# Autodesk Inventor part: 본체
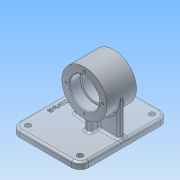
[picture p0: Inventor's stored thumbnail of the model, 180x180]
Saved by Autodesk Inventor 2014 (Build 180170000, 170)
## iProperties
Created: 2019-09
Part Number: 본체
Material: 알루미늄 6061
Document SubType Name: Modeling
Designer: net
Density: 2.71 g/cm^3
Appearance: 알루미늄 - 평지
Mass: 556.75 g
Surface Area: 497.149 cm^2
Volume: 205.443 cm^3
Author: net
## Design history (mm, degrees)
sketch "스케치1"
  geometry: L1 (-21, 0)-(21, 0); L2 (-21, 21)-(-6.3, 21); L3 (-6, 20.7)-(-6, 18); L4 (-6, 18)-(6, 18); L5 (6, 18)-(6, 20.7); L6 (6.3, 21)-(21, 21); L7 (21, 21)-(21, 32); L8 (21, 32)-(-21, 32); L9 (-21, 32)-(-21, 21); A1 r 0.3 centre (-6.3, 20.7) between (-6, 20.7) and (-6.3, 21); A2 r 0.3 centre (6.3, 20.7) between (6.3, 21) and (6, 20.7); 5 further points
  constraints: 18 end point, 6 parallel, 4 point on circle, 4 tangent, 3 collinear, 3 midpoint, 2 centre point, 2 point on line, 2 vertical alignment, 1 coincident, 1 equal radius, 1 horizontal, 1 perpendicular
  dimensions: "d0" = 42 distance of L1.start L1.end; "d1" = 15 distance of L2.start point (-6, 21); "d2" = 42 diameter of L2 L1; "d3" = 64 diameter of L8 L1; "d4" = 36 diameter of L4 L1; "d5" = 0.3 radius of A1
revolve "회전1" sketch "스케치1" stored, may be unused: angle "d6" = 90 deg
node "작업 평면1"
sketch "스케치2"
  geometry: L1 (21, 32)-(21, -32) reference; L2 (-21, 32)-(-21, -32) reference; L3 (51, -62)-(-51, -62); L4 (-63, -50)-(-63, 24); L5 (-51, 36)-(51, 36); L6 (63, 24)-(63, -50); L7 (21, -32)-(-21, -32) reference; L8 (21, 32)-(-21, 32) reference; A1 r 12 centre (51, 24) between (63, 24) and (51, 36); A2 r 12 centre (-51, 24) between (-51, 36) and (-63, 24); A3 r 12 centre (-51, -50) between (-63, -50) and (-51, -62); A4 r 12 centre (51, -50) between (51, -62) and (63, -50); 4 further points
  constraints: 8 end point, 8 point on circle, 8 tangent, 6 point on line, 4 centre point, 3 equal radius, 2 parallel, 1 horizontal, 1 perpendicular
  dimensions: "d8" = 98 distance of point (-63, -62) point (-63, 36); "d9" = 126 distance of point (63, -62) point (-63, -62); "d10" = 63 distance from line of L4 point (0, 0); "d11" = 62 distance from line of L3 point (0, 0); "d12" = 12 radius of A1
extrude "돌출1" join sketch "스케치2" distance "d13" = 9; taper "d14" = 0 deg
sketch "스케치3"
  geometry: L1 (4, -32)-(-4, -32); L2 (-4, -32)-(-4, 32); L3 (-4, 32)-(4, 32); L4 (4, 32)-(4, -32); L5 (4, -32)-(-4, 32); L6 (-4, -32)-(4, 32); L7 (-17, 4)-(17, 4); L8 (17, 4)-(17, -4); L9 (17, -4)-(-17, -4); L10 (-17, -4)-(-17, 4); L11 (-17, 4)-(17, -4); L12 (17, 4)-(-17, -4); L13 (-21, 32)-(21, 32) reference; L14 (-21, -32)-(21, -32) reference; 4 further points
  constraints: 24 end point, 6 midpoint, 4 parallel, 2 collinear, 2 horizontal, 2 perpendicular, 1 coincident
  dimensions: "d15" = 8 distance of L2.end L3.end; "d16" = 8 distance of L7.end L8.end (= d15); "d17" = 34 distance of L7.start L7.end
extrude "돌출2" join sketch "스케치3" stored distance "d18" = 9; taper "d19" = 0 deg
chamfer "모따기1" distance "d20" = 1; stored, may be unused: second distance "d21" = 2, angle "d22" = 45 deg
fillet "모깎기1" dims "d23" = 3
sketch "스케치4"
  geometry: A1 r 9 centre (51, -24) between (51, -33) and (60, -24) reference; A2 r 9 centre (51, 50) between (60, 50) and (51, 59) reference; A3 r 9 centre (-51, 50) between (-51, 59) and (-60, 50) reference; A4 r 9 centre (-51, -24) between (-60, -24) and (-51, -33) reference; 5 further points
  constraints: 4 coincident
hole "구멍1" sketch "스케치4" at (-51, 50), (51, 50), (51, -24), (-51, -24) diameter "d24" = 4.5; stored, may be unused: countersink angle "d28" = 90 deg, drill point angle "d30" = 118 deg; dims "d25" = 6, "d26" = 8, "d27" = 4.4, "d29" = 8
sketch "스케치5"
  geometry: C1 r 32 at (0, 0) reference; 1 further point
  constraints: 1 vertical alignment
  dimensions: "d31" = 26 distance of C1.centre point (0, 26)
hole "구멍2" sketch "스케치5" at (0, 26) diameter "d32" = 3.242; stored, may be unused: countersink angle "d36" = 90 deg, drill point angle "d38" = 118 deg; dims "d33" = 8, "d34" = 8, "d35" = 4.4, "d37" = 10
sketch "스케치6"
  geometry: L1 (51, 62)-(-51, 62) reference; L2 (63, -24)-(63, 50) reference; 2 further points
  constraints: 1 other
  dimensions: "d42" = 10 distance from line of L1 point (0, 52); "d43" = 63 distance from line of L2 point (0, 52)
feature "엠보싱1" sketch "스케치6" dims "d0" = 42, "d1" = 15, "d2" = 42, "d3" = 64, "d4" = 36, "d5" = 0.3, "d8" = 98, "d9" = 126, "d10" = 63, "d11" = 62, "d12" = 12, "d44" = 1, "d45" = 0
node "솔리드1"
pattern_circular "원형 패턴1" dims angle "d40" = 360 deg
mirror "대칭1"
node "투영된 루프1"
other parameters: "d7" = -59
